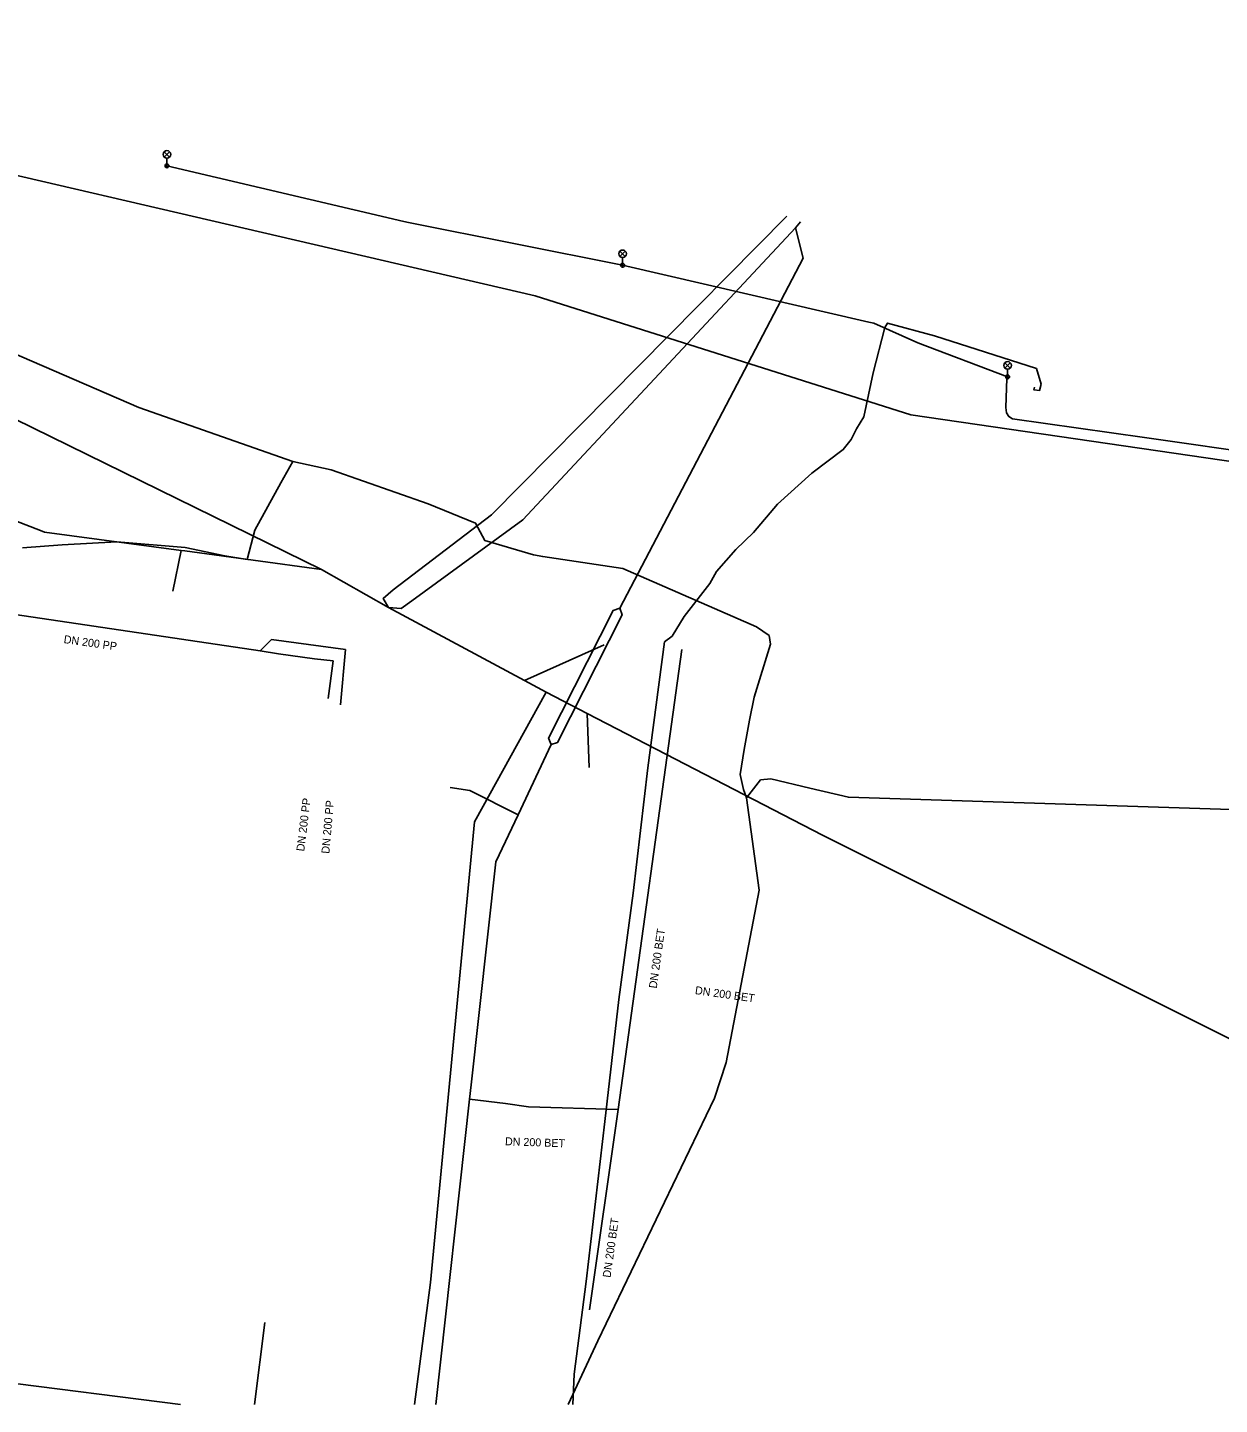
# Model space of a CAD drawing. Extents: x -598932 to -598196, y -1162210 to -1161504.
# Drawn here: x -598473 to -598353.7, y -1162207 to -1162069.3 of the extents above; entities that cross this region are included whole.
import ezdxf

# ---------------------------------------------------------------- set-up
doc = ezdxf.new("R2010")
doc.units = 0
for name, color, linetype in [('Vrstva 1', 7, 'Continuous'), ('Vrstva 12', 7, 'Continuous'), ('Vrstva 14', 7, 'Continuous'), ('Vrstva 33', 7, 'Continuous'), ('Vrstva 4', 7, 'Continuous'), ('Vrstva 5', 7, 'Continuous'), ('Vrstva 53', 7, 'Continuous'), ('Vrstva 55', 7, 'Continuous'), ('Vrstva 8', 7, 'Continuous'), ('Vrstva 9', 7, 'Continuous')]:
    doc.layers.add(name, color=color, linetype=linetype)

msp = doc.modelspace()

# ---------------------------------------------------------------- linework, layer by layer
at = {"layer": 'Vrstva 1'}
for p, q in [((-598423.426, -1162118.508), (-598396.128, -1162089.307)), ((-598396.128, -1162089.307), (-598395.652, -1162088.704)), ((-598395.37, -1162092.33), (-598396.128, -1162089.307)), ((-598413.725, -1162127.347), (-598395.37, -1162092.33)), ((-598458.434, -1162125.624), (-598457.583, -1162121.567)), ((-598415.27, -1162130.99), (-598423.262, -1162134.576)), ((-598407.521, -1162131.476), (-598413.898, -1162177.458)), ((-598416.8, -1162143.28), (-598416.992, -1162137.864)), ((-598423.901, -1162148.006), (-598420.577, -1162140.96)), ((-598430.704, -1162145.275), (-598428.728, -1162145.566)), ((-598428.728, -1162145.566), (-598423.901, -1162148.006)), ((-598426.11, -1162152.69), (-598423.901, -1162148.006)), ((-598425.15, -1162176.866), (-598428.745, -1162176.437)), ((-598422.866, -1162177.2), (-598425.15, -1162176.866)), ((-598413.898, -1162177.458), (-598422.866, -1162177.2)), ((-598416.745, -1162197.503), (-598413.898, -1162177.458))]:
    msp.add_line(p, q, dxfattribs=at)
for points in [[(-598436.849, -1162127.258), (-598437.376, -1162126.357), (-598436.4, -1162125.493), (-598426.542, -1162117.998), (-598397.019, -1162088.149)], [(-598436.849, -1162127.258), (-598435.574, -1162127.371), (-598434.522, -1162126.582), (-598423.426, -1162118.508)], [(-598420.577, -1162140.96), (-598420.836, -1162140.33), (-598414.383, -1162127.554), (-598413.725, -1162127.347)], [(-598420.577, -1162140.96), (-598419.944, -1162140.78), (-598413.491, -1162128.005), (-598413.725, -1162127.347)], [(-598432.131, -1162206.96), (-598428.745, -1162176.437), (-598428.585, -1162174.993), (-598426.11, -1162152.69)]]:
    msp.add_lwpolyline(points, dxfattribs=at)
at = {"layer": 'Vrstva 12'}
for p, q in [((-598450.254, -1162206.96), (-598449.223, -1162198.78)), ((-598477.39, -1162204.47), (-598457.657, -1162206.96))]:
    msp.add_line(p, q, dxfattribs=at)
at = {"layer": 'Vrstva 14'}
msp.add_lwpolyline([(-598217.743, -1162202.648), (-598218.334, -1162201.688), (-598338.63, -1162114.69), (-598384.62, -1162107.99), (-598422.17, -1162096.1), (-598509.221, -1162075.902), (-598509.921, -1162075.996), (-598510.741, -1162076.086), (-598530.41, -1162081.101), (-598553.423, -1162069.27)], dxfattribs=at)
at = {"layer": 'Vrstva 33'}
for p, q in [((-598459.282, -1162081.687), (-598458.752, -1162082.217)), ((-598459.282, -1162082.217), (-598458.752, -1162081.687)), ((-598459.017, -1162083.102), (-598459.017, -1162082.327)), ((-598413.704, -1162091.628), (-598413.174, -1162092.158)), ((-598413.704, -1162092.158), (-598413.174, -1162091.628)), ((-598413.439, -1162093.043), (-598413.439, -1162092.268)), ((-598375.189, -1162102.789), (-598374.659, -1162103.319)), ((-598375.189, -1162103.319), (-598374.659, -1162102.789)), ((-598374.924, -1162104.204), (-598374.924, -1162103.429))]:
    msp.add_line(p, q, dxfattribs=at)
for centre, radius in [((-598459.017, -1162081.952), 0.375), ((-598459.017, -1162083.102), 0.19), ((-598459.017, -1162083.102), 0.05), ((-598413.439, -1162091.893), 0.375), ((-598413.439, -1162093.043), 0.19), ((-598413.439, -1162093.043), 0.05), ((-598374.924, -1162103.054), 0.375), ((-598374.924, -1162104.204), 0.19), ((-598374.924, -1162104.204), 0.05)]:
    msp.add_circle(centre, radius, dxfattribs=at)
at = {"layer": 'Vrstva 5'}
for p, q in [((-598449.697, -1162131.613), (-598474.208, -1162127.96)), ((-598448.551, -1162130.479), (-598449.697, -1162131.613)), ((-598441.159, -1162131.467), (-598448.551, -1162130.479)), ((-598447.865, -1162131.893), (-598449.697, -1162131.613)), ((-598444.258, -1162132.41), (-598447.865, -1162131.893)), ((-598442.396, -1162132.612), (-598444.258, -1162132.41)), ((-598441.656, -1162136.998), (-598441.159, -1162131.467)), ((-598442.882, -1162136.369), (-598442.396, -1162132.612)), ((-598428.24, -1162148.69), (-598421.087, -1162135.747)), ((-598432.64, -1162194.76), (-598428.24, -1162148.69)), ((-598434.251, -1162206.96), (-598432.64, -1162194.76))]:
    msp.add_line(p, q, dxfattribs=at)
at = {"layer": 'Vrstva 53'}
for p, q in [((-598401.34, -1162145.45), (-598401.67, -1162143.98)), ((-598394.719, -1162145.318), (-598398.61, -1162144.39)), ((-598401.34, -1162145.45), (-598401.05, -1162146.3))]:
    msp.add_line(p, q, dxfattribs=at)
for points in [[(-598446.41, -1162112.67), (-598461.84, -1162107.26), (-598487.49, -1162096.18), (-598497.21, -1162091.83), (-598500.77, -1162090.52), (-598523.82, -1162080.22), (-598538, -1162074.7)], [(-598446.41, -1162112.67), (-598447.61, -1162114.79), (-598450.22, -1162119.54), (-598451.01, -1162122.47)], [(-598400.73, -1162138.53), (-598400.29, -1162136.23), (-598398.65, -1162130.92), (-598398.78, -1162130.07), (-598400.05, -1162129.19), (-598413.4, -1162123.37), (-598421.43, -1162122.18), (-598422.35, -1162122), (-598427.21, -1162120.58), (-598428.15, -1162118.84), (-598432.9, -1162116.91), (-598442.6, -1162113.51), (-598446.41, -1162112.67)], [(-598451.01, -1162122.47), (-598453.23, -1162122.09), (-598457.18, -1162121.27), (-598464.02, -1162120.71), (-598469.51, -1162121), (-598473.48, -1162121.31)], [(-598401.67, -1162143.98), (-598401.29, -1162141.47), (-598400.73, -1162138.53)], [(-598338.99, -1162142.35), (-598339.44, -1162143.66), (-598340.4, -1162144.75), (-598342.42, -1162145.94), (-598343.4, -1162147.16), (-598344.337, -1162147.739), (-598390.85, -1162146.24), (-598394.719, -1162145.318)], [(-598398.61, -1162144.39), (-598399.63, -1162144.51), (-598401.05, -1162146.3)], [(-598401.05, -1162146.3), (-598399.78, -1162155.53), (-598403.07, -1162172.75), (-598404.26, -1162176.34), (-598415.93, -1162200.59), (-598418.889, -1162206.96)]]:
    msp.add_lwpolyline(points, dxfattribs=at)
at = {"layer": 'Vrstva 55'}
for points in [[(-598374.782, -1162104.274), (-598374.924, -1162104.204), (-598383.91, -1162100.809), (-598388.322, -1162098.845), (-598388.809, -1162098.732), (-598413.439, -1162093.043), (-598434.847, -1162088.769), (-598435.334, -1162088.655), (-598459.017, -1162083.102)], [(-598409.25, -1162130.69), (-598408.47, -1162130.13), (-598407.29, -1162128.16), (-598404.7, -1162124.88), (-598404.03, -1162123.67), (-598402.1, -1162121.45), (-598400.35, -1162119.77), (-598397.95, -1162116.92), (-598394.52, -1162113.82), (-598391.37, -1162111.47), (-598390.58, -1162110.45), (-598390.03, -1162109.39), (-598389.3, -1162108.2), (-598388.37, -1162103.81), (-598387.21, -1162099.26), (-598386.94, -1162098.83), (-598382.24, -1162100.1), (-598372.05, -1162103.38), (-598371.56, -1162104.93), (-598371.73, -1162105.55), (-598372.29, -1162105.51), (-598372.239, -1162105.246)], [(-598341.14, -1162108.35), (-598343.52, -1162108.96), (-598346.98, -1162110.3), (-598348.65, -1162112.05), (-598361.23, -1162110.269), (-598374.43, -1162108.4), (-598374.82, -1162108.17), (-598375.03, -1162107.79), (-598375.12, -1162107.25), (-598375.02, -1162104.38), (-598374.782, -1162104.274)], [(-598418.41, -1162206.96), (-598418.27, -1162203.94), (-598417.07, -1162194.67), (-598415.23, -1162178.67), (-598413.8, -1162166.46), (-598412.38, -1162155.82), (-598410.93, -1162143.29), (-598409.25, -1162130.69)]]:
    msp.add_lwpolyline(points, dxfattribs=at)
at = {"layer": 'Vrstva 9'}
for p, q in [((-598505.417, -1162093.152), (-598443.56, -1162123.451)), ((-598443.56, -1162123.451), (-598436.85, -1162127.258)), ((-598393.434, -1162150.043), (-598344.226, -1162174.649))]:
    msp.add_line(p, q, dxfattribs=at)
for points in [[(-598507.86, -1162105.54), (-598490.979, -1162112.077), (-598490.851, -1162112.127), (-598490.515, -1162112.257), (-598488.097, -1162113.197), (-598471.498, -1162119.639), (-598471.26, -1162119.73)], [(-598471.26, -1162119.73), (-598457.583, -1162121.567), (-598457.237, -1162121.614), (-598443.56, -1162123.451)], [(-598436.85, -1162127.258), (-598423.262, -1162134.576), (-598421.087, -1162135.747)], [(-598421.087, -1162135.747), (-598416.992, -1162137.864), (-598393.434, -1162150.043)]]:
    msp.add_lwpolyline(points, dxfattribs=at)

# ---------------------------------------------------------------- texts
at = {"layer": 'Vrstva 4'}
for rotation, p in [(82, (-598410.029, -1162165.394)), (352, (-598406.236, -1162165.914)), (358, (-598425.214, -1162181.036)), (82, (-598414.648, -1162194.317))]:
    msp.add_text('DN 200 BET', height=0.8, rotation=rotation, dxfattribs=at).set_placement(p)
at = {"layer": 'Vrstva 8'}
for rotation, p in [(352, (-598469.382, -1162130.815)), (83, (-598445.288, -1162151.683)), (85, (-598442.777, -1162151.911))]:
    msp.add_text('DN 200 PP', height=0.8, rotation=rotation, dxfattribs=at).set_placement(p)

doc.saveas('drawing.dxf')
